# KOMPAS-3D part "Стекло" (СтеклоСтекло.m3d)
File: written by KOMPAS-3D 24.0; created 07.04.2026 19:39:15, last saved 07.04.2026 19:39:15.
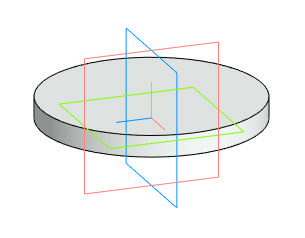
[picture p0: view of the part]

Document properties: Автор: Main; Полное имя файла: D:\DN.ru Аутсерс\Стекло смотровое DN.ru\Исходники\Стекло смотровое DN.ru SG2-34G-F тип В ГОСТ 21836-2021 Ду50 Ру40, углеродистая сталь, фланцевое\СтеклоСтекло.m3d

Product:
- Body: Твердое тело1  | qty 1
- Part/product: Стекло

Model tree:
1. Твердое тело1  (labels: Твердое тело1)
